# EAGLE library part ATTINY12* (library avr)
MICROCONTROLLER 1 Kbytes FLASH 64 bytes EEPROM
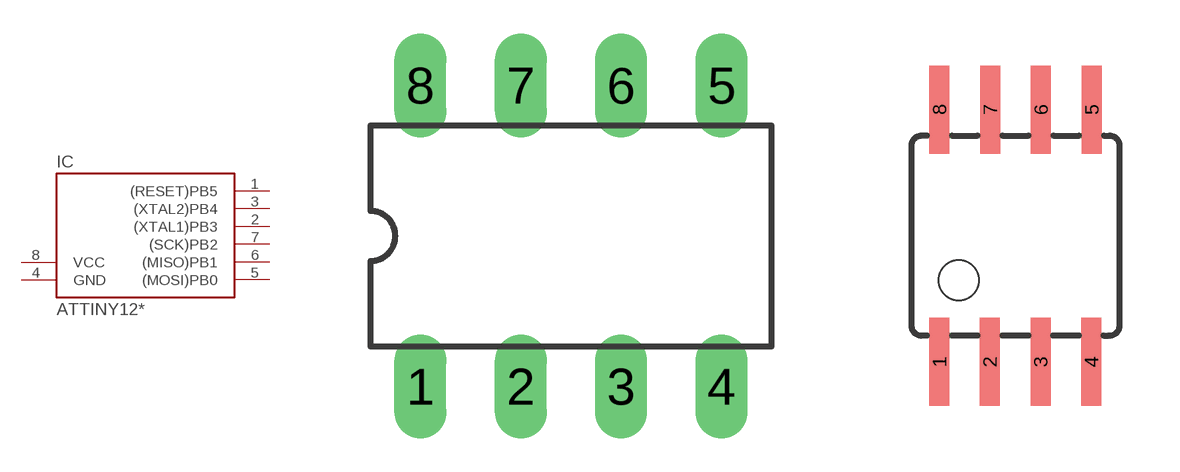
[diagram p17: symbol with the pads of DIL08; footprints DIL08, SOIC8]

Designator prefix IC

## ATTINY12-8P, ATTINY12L-4P, ATTINY12V-1P  [DIL08]
1  (RESET)PB5
2  (XTAL1)PB3
3  (XTAL2)PB4
4  GND  pwr
5  (MOSI)PB0
6  (MISO)PB1
7  (SCK)PB2
8  VCC  pwr

## ATTINY12-8S, ATTINY12L-4S, ATTINY12V-1S  [SOIC8]
Pads as for DIL08

## Footprint DIL08 (pad centres in mm)
Dual In Line
drill 0.813 long: 1 -3.81,-3.81; 2 -1.27,-3.81; 3 1.27,-3.81; 4 3.81,-3.81; 5 3.81,3.81; 6 1.27,3.81; 7 -1.27,3.81; 8 -3.81,3.81

## Footprint SOIC8 (pad centres in mm)
Wide Plastic Gull Wing Small Outline Package
smd 0.5 x 2.2: 1 -1.905,-3.154; 2 -0.645,-3.154; 3 0.625,-3.154; 4 1.895,-3.154; 5 1.905,3.154; 6 0.635,3.154; 7 -0.635,3.154; 8 -1.905,3.154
